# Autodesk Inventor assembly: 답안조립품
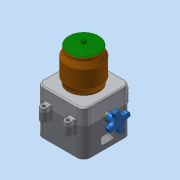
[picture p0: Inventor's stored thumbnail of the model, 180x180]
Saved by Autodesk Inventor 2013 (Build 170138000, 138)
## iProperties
Created: 2018-01
Part Number: 답안조립품
Document SubType Name: Assembly
Designer: dgall
Author: dgall
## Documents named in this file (9)
- C:\Users\dgall\Desktop\480107V1047\OldVersions\답안조립품.iam
- C:\Users\dgall\Desktop\480107V1047\본체.ipt
- C:\Users\dgall\Desktop\480107V1047\핸들축.ipt
- C:\Users\dgall\Desktop\480107V1047\볼트 M3x12.ipt
- C:\Users\dgall\Desktop\480107V1047\핸들.ipt
- C:\Users\dgall\Desktop\480107V1047\본체커버.ipt
- C:\Users\dgall\Desktop\480107V1047\용기.ipt
- C:\Users\dgall\Desktop\480107V1047\용기캡.ipt
- C:\Users\dgall\Desktop\480107V1047\볼트 M4x12.ipt
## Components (2 placed, 2 different names)
1. 핸들축:1
2. 핸들:1
